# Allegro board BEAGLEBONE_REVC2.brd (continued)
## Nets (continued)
GPIO1_16: P9.15(8) U5.R13(GPMC_A0/GMII2_TXEN/RGMII2_TCTL/)
GPIO1_17: P9.23(12) U5.V14(GPMC_A1/GMII2_RXDV/RGMII2_RCTL/)
GPIO1_28: P9.12(31) U5.U18(GPMC_BE1N/GMII2_COL/GPMC_CSN6/M)
GPIO1_29: P8.26(38) U5.V6(GPMC_CSN0/GPIO1_29)
GPIO1_30: P8.21(11) U5.U9(GPMC_CSN1/GPMC_CLK/MMC1_CLK/PRT)
GPIO1_31: P8.20(35) U5.V9(GPMC_CSN2/GPMC_BE1N/MMC1_CMD/PR)
GPIO2_1: P8.18(34) U5.V12(GPMC_CLK/LCD_MEM_CLK/GPMC_WAIT1)
GPIO2_6: P8.45(23) R80.2 R100.1 U5.R1(LCD_DATA0/GPMC_A0//EHRPWM2A//PR)
GPIO2_7: P8.46(48) R81.2 R101.1 U5.R2(LCD_DATA1/GPMC_A1//EHRPWM2B//PR)
GPIO2_8: P8.43(22) R82.2 R102.1 U5.R3(LCD_DATA2/GPMC_A2//EHRPWM2_TRIP)
GPIO2_9: P8.44(47) R83.2 R103.1 U5.R4(LCD_DATA3/GPMC_A3//EHRPWM2_SYNC)
GPIO2_10: P8.41(21) R84.2 R104.1 U5.T1(LCD_DATA4/GPMC_A4//EQEP2A_IN//P)
GPIO2_11: P8.42(46) R85.2 R105.1 U5.T2(LCD_DATA5/GPMC_A5//EQEP2B_IN//P)
GPIO2_12: P8.39(20) R86.2 R106.1 U5.T3(LCD_DATA6/GPMC_A6/PR1_EDIO_DATA)
GPIO2_13: P8.40(45) R87.2 R107.1 U5.T4(LCD_DATA7/GPMC_A7/PR1_EDIO_DATA)
GPIO2_22: P8.27(14) U5.U5(LCD_VSYNC/GPMC_A8//PR1_EDIO_DAT)
GPIO2_23: P8.29(15) U5.R5(LCD_HSYNC/GPMC_A9//PR1_EDIO_DAT)
GPIO2_24: P8.28(39) U5.V5(LCD_PCLK/GPMC_A10//PR1_EDIO_DAT)
GPIO2_25: P8.30(40) U5.R6(LCD_AC_BIAS_EN/GPMC_A11//PR1_ED)
GPIO3_18: R202.2 U5.B12(MCASP0_ACLKR/EQEP0A_IN/MCASP0_A)
GPIO3_19: P9.27(14) U5.C13(MCASP0_FSR/EQEP0B_IN/MCASP0_AXR)
GPIO3_20: R221.2 U5.D13(MCASP0_AXR1/EQEP0_INDEX//MCASP1)
GPIO3_21: P9.25(13) U5.A14(MCASP0_AHCLKX/EQEP0_STROBE/MCAS)
GRN_C: P10.10(GRNC) R128.2
GRNA: P10.9(GRNA) U15.3(LED1/REGOFF)
HS_IND: TP8.1(TP) U11.16(HS_IND)
HUB_BIAS: R157.1 U11.26(RBIAS)
I2C0_SCL: R7.2 U2.28(SCL) U5.C16(I2C0_SCL/TIMER7/UART2_RTSN/ECAP) U7.6(SCL)
I2C0_SDA: R4.2 U2.27(SDA) U5.C17(I2C0_SDA/TIMER4/UART2_CTSN/ECAP) U7.5(SDA)
I2C1_SCL: P9.17(9) U5.A16(SPI0_CS0/MMC2_SDWP/I2C1_SCL/EHR)
I2C1_SDA: P9.18(34) U5.B16(SPI0_D1/MMC1_SDWP/I2C1_SDA/EHRP)
I2C2_SCL: P9.19(10) U5.D17(UART1_RTSN/TIMER5/DCAN0_RX/I2C2)
I2C2_SDA: P9.20(35) U5.D18(UART1_CTSN/TIMER6/DCAN0_TX/I2C2)
JTAG_EMU0: P7.13(EMU0) R170.2 R176.2 U5.C14(EMU0/GPIO3_7)
JTAG_EMU1: P7.14(EMU1) R171.2 R179.2 U5.B14(EMU1/GPIO3_8)
JTAG_TCK: R164.2 R178.1 R180.1 U5.A12(TCK)
JTAG_TDI: P7.3(TDI) R165.2 U5.B11(TDI)
JTAG_TDO: P7.7(TDO) R166.2 U5.A11(TDO)
JTAG_TMS: P7.1(TMS) R168.2 U5.C11(TMS)
JTAG_TRSTN: P7.2(TRSTN) R169.2 R186.1 U5.B10(NTRST)
LDO3: R19.1 U2.40(LDO3)
LDO4: R121.1 U2.43(LDO4)
LDO_PGOOD: R141.2 U2.46(LDO_PGOOD)
LED2: P10.12(YELA) R219.1 U15.2(LED2/NINTSEL)
LEDAA: D2.2(A) R96.2 TP10.1(TP)
LEDAC: D2.1(C) Q1.6(3)
LEDBA: D3.2(A) R97.2 TP11.1(TP)
LEDBC: D3.1(C) Q1.3
LEDCA: D4.2(A) R98.2 TP12.1(TP)
LEDCC: D4.1(C) Q2.6(3)
LEDDA: D5.2(A) R99.2 TP13.1(TP)
LEDDC: D5.1(C) Q2.3
MDIO_CLK: U5.M18(MDIO_CLK/TIMER5/UART5_TXD/UART3) U15.17(MDC)
MDIO_DATA: R131.2 U5.M17(MDIO_DATA/TIMER6/UART5_RXD/UART) U15.16(MDIO)
MMC0_CLKO: P4.5(CLOCK) R192.2 U5.G17(MMC0_CLK/GPMC_A24/UART3_CTSN/UA)
MMC0_CMD: P4.3(CMD) R191.2 U5.G18(MMC0_CMD/GPMC_A25/UART3_RTSN/UA)
MMC0_DAT0: P4.7(DAT0) R193.2 U5.G16(MMC0_DAT0/GPMC_A23/UART5_RTSN/U)
MMC0_DAT1: P4.8(DAT1) R194.2 U5.G15(MMC0_DAT1/GPMC_A22/UART5_CTSN/U)
MMC0_DAT2: P4.1(DAT2) R190.2 U5.F18(MMC0_DAT2/GPMC_A21/UART4_RTSN/T)
MMC0_DAT3: P4.2(CD/DAT3) R195.2 U5.F17(MMC0_DAT3/GPMC_A20/UART4_CTSN/T)
NINT/RXCLK/PHYAD1: R215.1 R216.1
NON_REM1: R154.2 R158.1 U11.13(NON_REM1)
NON_REM2: R155.2 R159.1 TP7.1(TP) U11.19(SUSP_IND/NON_REM0)
OSC0_IN: C26.1 R21.1 U5.V10(OSC0_IN) Y2.3 Y3.3
OSC0_OUT: R24.2 U5.U11(OSC0_OUT)
OSC0_OUT1: C27.1 R21.2 R24.1 Y2.1 Y3.1
OSC1_IN: C23.2 U5.A6(OSC1_IN) Y1.1
OSC1_OUT: R22.2 U5.A4(OSC1_OUT)
OSC1_OUT1: C24.2 R22.1 Y1.2
P_BYPASS: C5.2 U2.47(BYPASS)
P_INT_LDO: C4.2 U2.48(INT_LDO)
P_L1: L1.1 U2.20(L1)
P_L2: L2.1 U2.23(L2)
P_L3: L3.1 U2.31(L3)
P_MUXIN: R1.2 R2.1 U2.14(MUX_IN)
P_MUXOUT: R8.2 U2.16(MUX_OUT)
P_WAKEUP: R11.1 U2.13(WAKEUP)
PDDR_A0: R29.2 U5.F3(DDR_A0)
PDDR_A1: R25.2 U5.H1(DDR_A1)
PDDR_A2: R30.2 U5.E4(DDR_A2)
PDDR_A3: R26.2 U5.C3(DDR_A3)
PDDR_A4: R31.2 U5.C2(DDR_A4)
PDDR_A5: R32.2 U5.B1(DDR_A5)
PDDR_A6: R33.2 U5.D5(DDR_A6)
PDDR_A7: R34.2 U5.E2(DDR_A7)
PDDR_A8: R35.2 U5.D4(DDR_A8)
PDDR_A9: R36.2 U5.C1(DDR_A9)
PDDR_A10: R37.2 U5.F4(DDR_A10)
PDDR_A11: R38.2 U5.F2(DDR_A11)
PDDR_A12: R39.2 U5.E3(DDR_A12)
PDDR_A13: R40.2 U5.H3(DDR_A13)
PDDR_BA0: R41.2 U5.C4(DDR_BA0)
PDDR_BA1: R42.2 U5.E1(DDR_BA1)
PDDR_BA2: R43.2 U5.B3(DDR_BA2)
PDDR_CASN: R64.2 U5.F1(DDR_CASN)
PDDR_CKE: R62.2 U5.G3(DDR_CKE)
PDDR_CLK: R60.2 U5.D2(DDR_CK)
PDDR_CLKN: R61.2 U5.D1(DDR_NCK)
PDDR_CSN: R63.2 U5.H2(DDR_CSN0)
PDDR_D0: R44.2 U5.M3(DDR_D0)
PDDR_D1: R45.2 U5.M4(DDR_D1)
PDDR_D2: R46.2 U5.N1(DDR_D2)
PDDR_D3: R47.2 U5.N2(DDR_D3)
PDDR_D4: R48.2 U5.N3(DDR_D4)
PDDR_D5: R49.2 U5.N4(DDR_D5)
PDDR_D6: R50.2 U5.P3(DDR_D6)
PDDR_D7: R51.2 U5.P4(DDR_D7)
PDDR_D8: R52.2 U5.J1(DDR_D8)
PDDR_D9: R53.2 U5.K1(DDR_D9)
PDDR_D10: R54.2 U5.K2(DDR_D10)
PDDR_D11: R55.2 U5.K3(DDR_D11)
PDDR_D12: R56.2 U5.K4(DDR_D12)
PDDR_D13: R57.2 U5.L3(DDR_D13)
PDDR_D14: R58.2 U5.L4(DDR_D14)
PDDR_D15: R59.2 U5.M1(DDR_D15)
PDDR_DQM0: R67.2 U5.M2(DDR_DQM0)
PDDR_DQM1: R70.2 U5.J2(DDR_DQM1)
PDDR_DQS0: R68.2 U5.P1(DDR_DQS0)
PDDR_DQS1: R71.2 U5.L1(DDR_DQS1)
PDDR_DQSN0: R69.2 U5.P2(DDR_DQSN0)
PDDR_DQSN1: R72.2 U5.L2(DDR_DQSN1)
PDDR_ODT: R73.2 U5.G1(DDR_ODT)
PDDR_RASN: R65.2 U5.G4(DDR_RASN)
PDDR_WEN: R66.2 U5.B2(DDR_WEN)
PHY_VDDCR: C124.1 C125.1 U15.6(VDDCR)
PHY_XTAL1: C132.1 R140.2 R199.1 Y4.1
PHY_XTAL2: R140.1 R144.1 U15.4(XTAL2)
PHYX: C131.1 R144.2 Y4.2
PLLFILT: C145.1 U11.25(PLLFILT)
PMIC_INT: R10.2 R28.2 U5.B18(NNMI)
PMIC_INT_PU: R28.1 U14.7(2Y)
PMIC_INT_SRC: R10.1 R203.2 U2.45(INT) U14.1(2A) U14.2(2B)
PMIC_PGOOD: C25.1 R20.1 U2.26(PGOOD) U5.B15(PORZ)
PMIC_POWR_EN: U2.9(PWR_EN) U5.C6(PMIC_POWER_EN)
PWR_BUT: P9.9(5) U2.25(PB_IN)
PWR_LED: R6.1 U2.1(VLDO2)
PWR_LEDR: D1.2(A) R6.2 TP14.1(TP)
RBIAS: R145.1 U15.32(RBIAS)
RCLKIN: R199.2 R200.2 U15.5(XTAL1/CLKIN)
REFCLKO: R136.2 R209.2 U15.7(RXCLK/PHYAD1)
REMU_RSTN: R172.2 R182.1 U16.1(1A)
RESETN: C136.1 R156.2 U11.17(R\E\S\E\T\)
RMII1_COL: R207.1 U5.H16(GMII1_COL/RMII2_REFCLK/SPI1_SCL)
RMII1_CRS_DV: R139.1 U5.H17(GMII1_CRS/RMII1_CRS_DV/SPI1_D0/)
RMII1_REFCLK: R200.1 R201.2 R209.1
RMII1_RXCLK: R136.1 U5.L18(GMII1_RXCLK/UART2_TXD/RGMII1_RC)
RMII1_RXD0: R135.1 U5.M16(GMII1_RXD0/RMII1_RXD0/RGMII1_RD)
RMII1_RXD1: R132.1 U5.L15(GMII1_RXD1/RMII1_RXD1/RGMII1_RD)
RMII1_RXD2: R153.1 U5.L16(GMII1_RXD2/UART3_TXD/RGMII1_RD2)
RMII1_RXD3: R205.1 U5.L17(GMII1_RXD3/UART3_RXD/RGMII1_RD3)
RMII1_RXDV: R208.1 U5.J17(GMII1_RXDV/LCD_MEMORY_CLK/RGMII)
RMII1_RXERR: R137.1 U5.J15(GMII1_RXERR/RMII1_RXERR/SPI1_D1)
RMII1_TXCLK: R206.1 U5.K18(GMII1_TXCLK/UART2_RXD/RGMII1_TC)
RMII1_TXD0: U5.K17(GMII1_TXD0/RMII1_TXD0/RGMII1_TD) U15.22(TXD0)
RMII1_TXD1: U5.K16(GMII1_TXD1/RMII1_TXD1/RGMII1_TD) U15.23(TXD1)
RMII1_TXD2: U5.K15(GMII1_TXD2/DCAN0_RX/RGMII1_TD2/) U15.24(TXD2)
RMII1_TXD3: U5.J18(GMII1_TXD3/DCAN0_TX/RGMII1_TD3/) U15.25(TXD3)
RMII1_TXEN: U5.J16(GMII1_TXEN/RMII1_TXEN/RGMII1_TC) U15.21(TXEN)
RSVD3: R161.2 U11.15(VSS)
RTC_PORZ: R18.1 R141.1 R143.2 U5.B5(RTC_PORZ)
RTCK: P7.9(TCKRTN) R178.2
RXD0/MODE0: R124.1 R135.2 R198.1 U15.11(RXD0/MODE0)
RXD1/MODE1: R5.1 R123.1 R132.2 U15.10(RXD1/MODE1)
RXD2/RMIISEL: R153.2 R211.1 R212.1 U15.9(RXD2/RMIISEL)
RXD3/PHYAD2: R205.2 R213.1 R214.1 U15.8(RXD3/PHYAD2)
RXDV: R208.2 U15.26(RXDV)
RXER/PHYAD0: R125.1 R126.2 R137.2 U15.13(RXER/RXD4/PHYAD0)
RXN: C127.1 P10.2(RD-) R130.1 U15.30(RXN)
RXP: C126.1 P10.1(RD+) R129.1 U15.31(RXP)
SD_CD: P4.11(GND1) R196.1 R197.1
SPI1_CS0: P9.28(39) U5.C12(MCASP0_AHCLKR/EHRPWM0_SYNCI_O/M)
SPI1_D0: P9.29(15) U5.B13(MCASP0_FSX/EHRPWM0B//SPI1_D0/MM)
SPI1_D1: P9.30(40) U5.D12(MCASP0_AXR0/EHRPWM0_TRIPZONE_IN)
SPI1_SCLK: P9.31(16) U5.A13(MCASP0_ACLKX/EHRPWM0A//SPI1_SCL)
SYS_5V: C133.1 FB4.2 P9.7(4) P9.8(29) R3.2 R152.1 U2.7(SYS1) U2.8(SYS2) U9.2(IN#2) U9.3(IN#3)
SYS_RESETN: P9.10(30) R23.2 R27.1 U5.A10(NRESET_INOUT) U15.19(NRST)
SYS_VOLT: C6.1 C8.2 C9.2 C10.2 C17.2 C18.2 C19.2 R2.2 R3.1 U2.2(VINLDO) U2.21(VIN_DCDC1) U2.22(VIN_DCDC2) U2.32(VIN_DCDC3) U2.39(LDO3_IN) U2.42(LDO4_IN) U8.8(IN)
SYS_WARMRESETN: C101.1 R27.2 R163.2 S1.2(A2)
TCK: P7.11(TCK) R180.2
TCT_RCT: C130.1 P10.4(RCT) P10.5(TCT) R142.1
TDIS: P7.4(TDIS) R177.1
TESTOUT: TP6.1(TP) U5.A3(TESTOUT)
TIMER4: P8.7(4) U5.R7(GPMC_ADVN_ALE/TIMER4/GPIO2_2)
TIMER5: P8.9(5) U5.T6(GPMC_BE0N_CLE/TIMER5/GPIO2_5)
TIMER6: P8.10(30) U5.U6(GPMC_WEN/TIMER6/GPIO2_4)
TIMER7: P8.8(29) U5.T7(GPMC_OEN_REN/TIMER7/EMU4/GPIO2_)
TXCLK: R206.2 U15.20(TXCLK)
TXN: C129.1 P10.6(TD-) R134.1 U15.28(TXN)
TXP: C128.1 P10.3(TD+) R133.1 U15.29(TXP)
U5_H18: R201.1 U5.H18(RMII1_REFCLK/XDMA_EVENT_INTR2/S)
UART0_CTS: U5.E17(UART0_RTSN/UART4_TXD/DCAN1_RX/I) U12.40(BDBUS2)
UART0_RTS: U5.E18(UART0_CTSN/UART4_RXD/DCAN1_TX/I) U12.41(BDBUS3)
UART0_RX: U5.E16(UART0_TXD/SPI1_CS1/DCAN0_RX/I2C) U12.39(BDBUS1)
UART0_TX: U5.E15(UART0_RXD/SPI1_CS0/DCAN0_TX/I2C) U12.38(BDBUS0)
UART1_RXD: P9.26(38) U5.D16(UART1_RXD/MMC1_SDWP/DCAN1_TX/I2)
UART1_TXD: P9.24(37) U5.D15(UART1_TXD/MMC2_SDWP/DCAN1_RX/I2)
UART2_RXD: P9.22(36) U5.A17(SPI0_SCLK/UART2_RXD/I2C2_SDA/EH)
UART2_TXD: P9.21(11) U5.B17(SPI0_D0/UART2_TXD/I2C2_SCL/EHRP)
UART3_CTSN: P8.36(43) R90.2 R110.1 U5.U3(LCD_DATA10/GPMC_A14/EHRPWM1A/MC)
UART3_RTSN: P8.34(42) R91.2 R111.1 U5.U4(LCD_DATA11/GPMC_A15/EHRPWM1B/MC)
UART4_CTSN: P8.35(18) R92.2 R112.1 U5.V2(LCD_DATA12/GPMC_A16/EQEP1A_IN/M)
UART4_RTSN: P8.33(17) R93.2 R113.1 U5.V3(LCD_DATA13/GPMC_A17/EQEP1B_IN/M)
UART4_RXD: P9.11(6) U5.T17(GPMC_WAIT0/GM112_CRS/GPMC_CSN4/)
UART4_TXD: P9.13(7) U5.U17(GPMC_WPN/GMII2_RXERR/GPMC_CSN5/)
UART5_CTSN: P8.31(16) R94.2 R114.1 U5.V4(LCD_DATA14/GPMC_A18/EQEP1_INDEX)
UART5_RTSN: P8.32(41) R95.2 R115.1 U5.T5(LCD_DATA15/GPMC_A19/EQEP1_STROB)
UART5_RXD: P8.38(44) R89.2 R109.1 U5.U2(LCD_DATA9/GPMC_A13/EHRPWM1_SYNC)
UART5_TXD: P8.37(19) R88.2 R108.1 U5.U1(LCD_DATA8/GPMC_A12/EHRPWM1_TRIP)
USB0_DM: U5.N18(USB0_DM) U11.2(USBDM_DN2)
USB0_DP: U5.N17(USB0_DP) U11.3(USBDP_DN2)
USB0_ID: TP4.1(TP) U5.P16(USB0_ID)
USB0_VBUS: R152.2 U5.P15(USB0_VBUS) U16.4(2Y)
USB0_VBUS_PWR: U11.11(PRTPWR2) U16.3(2A)
USB1_DM: P2.2(P2) U5.R18(USB1_DM) U10.2(D-)
USB1_DP: P2.3(P3) U5.R17(USB1_DP) U10.1(D+)
USB1_DRVVBUS: R147.1 U5.F15(USB1_DRVVBUS/GPIO3_13) U9.4(EN)
USB1_ID: R146.1 U5.P17(USB1_ID)
USB1_OC: R148.2 U5.T16(GPMC_A10/GMII2_RXD1/RGMII2_RD1/) U9.5(O\C\)
USB1_VBUS: C134.1 P2.1(P1) U5.T18(USB1_VBUS) U9.6(OUT#6) U9.7(OUT#7) U9.8(OUT#8) U10.6(VBUS)
USB_DC: C2.1 P3.1(VB) R149.1 U2.12(USB)
USBDM_DN: P3.2(D-) U11.21(USBDM_UP)
USBDP_UP: P3.3(D+) U11.22(USBDP_UP)
USR0: Q1.2(5) R116.1 U5.V15(GPMC_A5/GMII2_TXD0/RGMII2_TD0/R)
USR1: Q1.5 R117.1 U5.U15(GPMC_A6/GMII2_TXCLK/RGMII2_TCLK)
USR2: Q2.2(5) R118.1 U5.T15(GPMC_A7/GMII2_RXCLK/RGMII2_RCLK)
USR3: Q2.5 R119.1 U5.V16(GPMC_A8/GMII2_RXD3/RGMII2_RD3/M)
VDCDC1: L1.2 R12.1 U2.19(VDCDC1)
VDCDC2: L2.2 R204.1 U2.24(VDCDC2)
VDCDC3: L3.2 R13.1 U2.29(VDCDC3)
VPP: U5.M5(VPP)
VREFP_ADC: C28.1 C29.1 C30.1 R78.2 U5.B9(VREFP)
VRTC: C20.1 C21.1 C98.1 R77.1 U2.3(VLDO1) U5.D7(VDDS_RTC) U17.1(2A) U17.2(2B) U17.8(VCC)
VRTC_DET: R17.1 U17.7(2Y)
VRTC_DET_OUT: R143.1 U17.3(2Y)
VRTC_DETB: C22.1 R17.2 U17.5(2A) U17.6(2B)
WAKEUP: R11.2 R77.2 U5.C5(EXT_WAKEUP)
WP: R210.2 TP2.1(TP) U7.7(WP)
XDMA_EVENT_INTR0: R183.1 U5.A15(EVENT_INTR0/TIMER4/CLKOUT1/SPI1)
XTALIN: C137.2 R160.1 U11.24(XTALIN/CLKIN) Y5.3
XTALOUT: C144.2 R160.2 U11.23(XTALOUT) Y5.1
XTIN: C153.2 U12.2(OSCIN) Y6.3(X3)
XTOUT: C155.2 U12.3(OSC0) Y6.1(X1)
YEL_C: P10.11(YELC) R16.2
N21360640: R220.1 U15.18(NINT/TXER/TXD4)

Pads without a net: NOREF 1; NOREF#11 1; NOREF#16 1; NOREF#25 1; NOREF#26 1; NOREF#27 1; P3 4; P5 3; P7 6; P10 7; U1 3; U2 15 17 44; U5 D3 F16 H4 M15 P18 R14 T13 U16 V17; U6 A2 E2 R3 R7; U8 2 6 7; U10 3 5; U11 5 8 12; U12 22 24 27 29 33 34 36 43 44 45 46 48 52 53 54 55 57 58 60; Y2 2 4; Y3 2 4; Y5 2 4; Y6 2 4

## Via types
v1: diameter 0.457, hole 0.203, TOP to BOTTOM, 799 vias
v2: diameter 0.559, hole 0.305, TOP to BOTTOM, 23 vias
v3: diameter 0.635, hole 0.305, TOP to BOTTOM, 5 vias

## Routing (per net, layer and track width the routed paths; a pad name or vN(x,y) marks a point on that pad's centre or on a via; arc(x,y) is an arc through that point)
3V3EXP_FB: length 6.3
  TOP w0.121: U8.3 12.95,8.88 12.7,8.64 v1(12.7,8.26)
  BOTTOM w0.121: C166.1 12.95,9.02 12.7,8.76 v1(12.7,8.26) 13.72,8.26 R150.1 R189.1
AGND: length 2.6
  TOP w0.203: U2.41 26,20.06 26.08,20.13 v1(26.08,20.95)
  BOTTOM w0.381: v1(26.08,20.95) 26.35,21.23 R15.1
DGND: length 423.3
  TOP w0.203: v2(26.8,16.51) 27,16.31 U2.30
  TOP w0.305: U12.25 v1(49.15,13.58) ; U17.4 31.88,21.79 32,21.67 v1(32,21.21) ; U12.47 41.84,17.73 v1(41.91,17.65) ; U5.A1 v1(56.33,26.8) ; v1(74.73,34.69) 74.33,34.29 U6.H8 ; v1(46.35,6.35) 46.35,6.79 46.33,6.81 U12.11 ; v1(46.35,6.35) v1(46.99,6.35) 47.12,6.35 47.33,6.57 U12.13 ; v1(46.35,6.35) 45.97,6.35 45.84,6.49 U12.10 ; v1(44.13,9.53) 43.33,8.73 U12.5 ; U5.H10 v1(48.73,33.49) U5.J10 ; v1(33.53,44.96) 33.77,45.2 Q1.4 ; v1(51.13,32.69) U5.H8 ; U5.L11 v1(47.93,35.89) U5.M12 ; v1(16.76,13.46) 16.5,13.2 U1.6 ; U5.A18 v1(42.33,27.09) ; v1(50.33,33.49) U5.J9 ; U6.A7 73.53,39.89 v1(73.93,39.49) U6.B8 ; Q1.1 32.27,47.51 v1(32.51,47.75) ; U5.M9 v1(50.33,36.69) U5.M8 ; U5.J11 v1(47.93,33.49) ; v1(73.93,33.09) 73.93,33.09 U6.J7 ; v1(47.13,31.89) U5.G12 47.69,32.13 48.17,32.13 U5.G11 ; U5.G9 v1(50.33,31.89) U5.F8 ; U5.M7 v1(51.93,35.89) U5.M6 ; U14.4 31.55,24.94 31.37,24.77 v1(31.11,24.77) ; v1(29.72,44.96) 29.96,45.2 Q2.4 ; U6.D8 v1(73.93,37.09) U6.E7 ; v1(47.62,17.65) 47.84,17.86 U12.35 ; U6.F2 v1(69.13,36.29) ; U5.J6 v1(52.73,33.49) U5.H6 ; v1(48.73,35.09) U5.K10 ; v1(48.73,35.09) U5.K11 ; v1(48.73,35.09) U5.L10 ; v1(50.33,35.09) U5.K9 ; U6.E3 v1(69.93,37.09) ; U12.51 38.56,16.09 38.35,15.88 v1(38.1,15.88) ; U6.B2 v1(69.13,39.49) ; U5.V1 v1(56.33,41.78) ; U6.N1 v1(68.33,29.89) ; U5.K7 U5.J7 v1(51.93,33.49) ; Q2.1 28.46,47.51 v1(28.7,47.75) ; U5.M14 v1(45.53,36.69) U5.N14 ; v1(47.13,32.69) U5.H12 ; v1(51.93,37.49) U5.N7 ; U5.L12 v1(47.13,35.89) U5.L13 ; U12.1 41.33,9.47 v1(41.27,9.53) ; U5.N10 v1(48.73,37.49) U5.N11 ; v2(22.23,40.01) 21.95,39.73 U11.6 ; v1(74.73,36.29) 74.33,35.89 U6.F8 ; v1(48.73,36.69) U5.M10 ; U5.V18 v1(41.91,41.09) ; v1(48.77,9.53) 48.33,9.09 U12.15 ; v1(51.13,33.49) U5.J8 ; U6.J3 v1(69.93,33.09) ; U5.G8 v1(50.33,32.69) U5.H9 ; U6.A3 v1(69.93,40.29) ; U1.2 v1(13.59,12.7) ; U6.D2 v1(69.13,37.89) ; U5.H7 v1(51.93,32.69) ; v1(49.15,14.61) 48.64,15.11 48.64,16.64 48.9,16.89 49.2,16.89 49.39,17.09 U12.32 ; U6.P9 v1(75.53,29.09) ; U6.H2 v1(69.13,34.69)
  TOP w0.381: C111.2 v1(79.25,37.09) ; C160.2 v1(80.52,35.56) ; C114.2 79.13,31.89 v1(79.25,32) ; R158.2 v1(27.56,42.55) ; C116.2 v1(64.33,42.55) ; C89.1 v1(79.69,42.55) ; C100.2 v1(11.94,48.26) ; C162.1 v1(38.1,19.56) ; C145.2 14.8,40.32 14.61,40.13 v1(14.61,39.69) ; v1(2.41,14.48) 2.41,15.49 D1.1 ; C110.2 78.91,38.69 v1(79.25,38.35) ; 36.83,41.27 36.83,42.29 37.08,42.55 C51.2 C52.1 ; 36.83,41.27 v1(36.83,40.64) v1(37.47,40.64) 37.47,41.15 C52.1 ; 36.83,41.27 C52.1 ; C117.2 v1(79.25,29.49) ; 64.77,45.85 v1(64.77,45.09) ; R79.1 v1(54.93,21.91) ; C163.1 38.61,6.99 v1(36.51,6.99) ; C101.2 6.99,42.16 6.73,42.42 v1(5.71,42.42) ; 48.58,45.85 v1(48.58,45.09) ; C113.2 v1(79.25,33.09) ; C159.2 v1(80.52,33.15) ; C146.2 v1(27.56,40.01) ; v3(14.73,8.32) 14.65,8.23 U8.4 ; U16.2 v1(30.86,41.91) ; C136.2 R159.2 v1(19.68,47.75) ; R161.1 v1(23.5,47.75) ; C137.1 v1(17.14,41.27) ; S1.1 2.16,41.13 v1(2.16,42.42) ; C112.2 v1(79.25,35.49) ; C144.1 v1(13.34,43.18) ; C109.2 v1(79.12,40.29) ; C115.2 v1(79.25,30.69)
  TOP w0.762: P2.4 70.54,20.34 C133.2
  LYR2_GND w0.889: TP1.1 61.69,21.05 ; TP1.1 61.69,19.59 ; TP1.1 60.23,21.05 ; TP1.1 60.23,19.59 ; 74.83,5.18 P9.46 ; P9.46 76.3,3.71 ; P9.46 74.83,3.71 ; P9.46 76.3,5.18 ; 73.76,2.64 P9.43 72.29,2.64 ; 72.29,3.71 P9.44 ; P9.44 72.29,5.18 ; P9.44 73.76,3.71 ; P9.44 73.76,5.18 ; P9.2 20.42,3.71 ; P9.2 18.95,5.18 ; P9.2 20.42,5.18 ; P9.2 18.95,3.71 ; P8.1 20.65,49.2 ; P8.1 18.72,49.2 ; P8.1 20.65,51.13 ; P8.1 18.72,51.13 ; P10.8 17.84,24.7 ; P10.8 17.84,26.1 ; P10.8 16.45,26.1 ; P10.8 16.45,24.7 ; 74.83,2.64 P9.45 76.3,2.64 ; 5.18,7.42 P5.2 ; P5.2 4.09,9.53 ; P5.2 6.27,9.53 ; P5.2 5.18,11.63 ; 20.42,51.97 P8.2 18.95,51.97 ; P2.4 74.15,21.11 ; P2.4 72.59,19.56 ; P2.4 72.59,21.11 ; P2.4 74.15,19.56 ; 20.65,2.87 P9.1 18.72,2.87
  BOTTOM w0.191: 29.75,32.86 31.78,32.86 31.94,33.02 R125.2
  BOTTOM w0.254: C82.2 49.5,28.58 48.73,29.35 v1(48.73,29.49) ; C62.1 46.44,31.2 v1(47.13,31.89) v1(47.13,32.69)
  BOTTOM w0.305: C39.2 51.64,33.78 v1(51.93,33.49) ; v1(48.73,33.49) 49.39,33.49 C40.2 ; v1(80.64,19.05) 80.51,18.91 U10.4 ; C93.2 52.73,30.98 v1(52.73,30.29) ; C91.2 52.73,34.18 v1(52.73,33.49) ; C45.2 47.82,31.89 v1(47.13,31.89) ; C58.1 v1(47.13,32.69) ; v1(51.93,35.89) C90.2 ; C92.2 v1(51.93,32.69) ; C64.1 50.04,31.6 v1(50.33,31.89) ; v1(50.33,35.09) 49.64,35.09 C38.2 ; v1(50.33,36.69) 50.04,36.98 C34.2 ; C96.2 v1(56.77,34.29) ; v1(44.13,9.53) R167.1 ; C37.2 48.44,34.8 v1(48.73,35.09) ; C41.2 v1(51.13,32.69) ; C35.2 51.24,37.49 v1(51.93,37.49) C65.1 ; C60.2 45.53,36 v1(45.53,36.69) 45.53,37.38 C33.2 ; C88.2 v1(47.93,35.89)
  BOTTOM w0.381: v1(24.77,5.84) 24.77,6.73 ; 24.77,6.73 25.91,6.73 26.16,6.99 26.16,8 ; 24.77,6.73 24.57,6.73 ; v1(51.13,43.18) C75.2 50.53,42.4 49.53,41.4 C43.1 ; R9.1 v1(28.26,20.32) C10.1 ; C149.1 31.37,41.4 v1(30.86,40.89) ; v2(23.5,15.24) 22.76,15.24 22.54,15.02 C2.2 21.84,14.48 21.46,14.86 C165.1 ; v2(23.5,16.51) 24.13,16.51 24.45,16.83 C17.1 C18.1 26.35,16.76 26.6,16.51 v2(26.8,16.51) ; C142.2 20.83,42.67 v2(20.95,42.55) ; C129.2 v1(10.67,27.94) ; C1.2 16.51,13.21 v1(16.76,13.46) ; R189.2 16.76,8 16.45,8.32 v3(15.75,8.32) ; R186.2 v1(59.63,6.99) ; C138.2 v2(22.23,42.55) ; R109.2 R108.2 v1(56.2,47.62) ; C156.2 62.1,15.24 v1(62.36,15.24) ; R146.2 41.25,39.09 40.51,38.35 v1(40.51,37.49) C78.2 ; C148.2 v1(44.13,14.61) ; U9.1 v1(75.59,13.63) ; C32.1 v1(37.21,32.77) ; v1(63.82,47.62) R100.2 R101.2 ; v1(54.93,21.91) 54.67,21.91 53.02,23.56 C97.2 C86.2 C98.2 C83.2 C85.2 C84.2 C57.2 46.74,24.26 46.48,24.51 v1(46.48,25.91) ; v1(76.71,37.85) 76.45,37.85 76.2,38.1 76.2,38.84 75.95,39.09 P4.9 ; C130.2 v1(10.67,30.48) ; v1(9.91,45.34) 9.19,46.05 P3.5 ; 20.32,8 20.32,6.6 v1(19.68,5.97) ; v1(36.83,40.64) v1(37.47,40.64) ; v1(36.83,40.64) 36.83,40.13 37.08,39.88 C61.2 37.47,40.01 v1(37.47,40.64) ; v1(36.83,40.64) 36.83,41.53 C69.2 37.47,41.66 v1(37.47,40.64) ; v1(14.61,39.69) 14.61,39.3 14.85,39.05 R157.2 ; C106.2 v1(65.28,35.49) ; R127.2 35.43,35.56 v1(35.18,35.81) ; U7.2 26.16,8 ; 26.16,8 26.16,9.27 ; U13.2 32.58,9.84 32.17,9.44 32.17,7.87 ; C54.2 37.21,25.78 v1(37.21,26.16) ; 71.82,13.34 v1(71.82,12.06) ; 71.82,13.34 69.7,13.34 ; 71.82,13.34 71.82,15.88 ; v1(71.82,12.06) P7.10 ; v1(71.82,12.06) v1(71.82,10.79) P7.8 ; R103.2 R102.2 v1(61.91,47.62) ; R147.2 v1(76.83,19.68) ; v1(36.2,14.86) C15.1 ; v1(48.77,9.53) 49.53,10.29 50.16,10.29 ; v1(19.05,23.75) C4.1 C5.1 ; v1(23.37,35.81) 23.37,35.31 23.94,34.73 C122.2 ; R128.1 v1(6.22,30.23) ; v1(6.22,30.23) v1(6.22,29.46) ; v1(6.22,30.23) 5.4,30.23 R138.1 5.4,29.46 v1(6.22,29.46) ; C147.2 49.37,15.37 49.15,15.14 v1(49.15,14.61) ; C155.1 v1(37.47,9.53) C153.1 ; C3.1 v1(10.16,13.97) C7.2 ; C76.2 C77.2 C79.2 41.42,27.67 41.91,27.18 41.91,27.09 ; C76.2 40.91,29.89 40.56,29.54 v1(40.51,29.54) ; C76.2 C49.2 ; v1(23.37,20.95) 23.62,21.21 23.62,21.65 C135.1 ; C164.1 v1(46.99,6.35) v1(46.35,6.35) 45.72,6.35 45.4,6.67 C161.2 ; R75.2 v1(64.01,33.66) ; R1.1 22.99,10.54 U7.4 25.91,10.54 26.16,10.29 26.16,9.27 ; v1(58.1,47.62) R106.2 R107.2 ; C66.1 v1(54.33,43.15) ; R118.2 v1(29.72,44.96) ; v1(65.28,33.09) C107.2 C118.2 ; v1(33.97,20.45) C50.1 32.85,19.3 ; C158.2 v1(42.86,6.35) ; C73.2 40.71,32.89 v1(40.51,32.69) ; C73.2 C71.1 40.91,33.89 v1(40.51,34.29) ; C73.2 C48.2 C49.2 ; v2(26.04,31.5) 26.42,31.11 26.42,30.61 C124.2 ; v2(26.04,31.5) 25.78,31.75 C120.2 C119.2 ; v2(26.04,31.5) 26.29,31.75 C125.2 ; v1(21.46,19.56) 22.23,19.56 C19.1 ; v1(19.68,29.53) R145.2 R216.2 ; R212.2 R5.2 R198.2 ; R212.2 R214.2 36.89,29.53 C31.1 37.3,29.12 v1(37.3,27.94) ; R212.2 v1(36.45,30.48) ; C63.1 42.42,41.4 42.11,41.09 v1(41.91,41.09) 41.62,41.09 41.42,40.89 C80.2 ; v1(6.22,29.46) R16.1 R219.2 ; v1(52.39,47.62) R113.2 R111.2 ; v1(60.01,47.62) R104.2 R105.2 ; C53.2 37.21,24 v1(37.21,23.75) ; C46.2 42.99,20.51 v1(42.99,20.32) ; C131.2 v1(21.46,25.53) ; C9.1 C8.1 26.1,15.24 v2(25.15,15.24) ; 48.58,45.85 v1(48.58,45.09) ; v1(50.48,47.62) R114.2 R115.2 ; R15.2 v1(26.35,23.81) ; 32.17,7.87 v1(33.15,7.87) ; 32.17,7.87 C102.2 ; v1(33.02,20.45) 32.85,20.28 32.85,19.3 ; R119.2 v1(28.7,47.75) ; C104.2 v1(65.28,38.69) ; C126.2 v1(10.67,34.29) ; R20.2 v1(29.21,27.3) ; R20.2 C157.1 ; R20.2 C25.2 ; v1(40.51,35.89) C81.2 C36.2 ; C108.2 v1(65.28,28.29) ; C128.2 v1(10.67,31.75) ; R117.2 v1(32.51,47.75) ; C103.2 v1(65.28,40.29) ; P4.6 80.76,35.32 v1(80.52,35.56) ; C150.2 v1(41.91,17.65) ; C20.2 v1(19.68,20.32) ; C152.2 46.04,14.85 45.79,14.61 v1(45.34,14.61) ; C21.2 v1(34.92,21.21) ; C94.2 v1(79.69,42.55) ; C95.2 v1(64.33,42.55) ; C134.2 v1(81.92,19.68) ; P7.16 71.82,15.88 ; 71.82,15.88 71.82,18.1 71.5,18.41 P7.20 ; C121.2 25.78,33.02 v2(26.04,33.27) 26.29,33.02 C123.2 27.11,33.4 27.37,33.66 28.96,33.66 29.75,32.86 ; R177.2 C154.2 v1(59.63,9.53) ; v1(54.29,47.62) R112.2 R110.2 ; C22.2 v1(33.97,23.81) ; C70.1 v1(52.73,43.18) ; v2(19.68,40.01) 19.56,39.88 C143.2 ; C127.2 v1(10.67,33.02) ; C105.2 v1(65.28,37.09) ; v1(40.51,31.19) 40.51,31.09 40.71,30.89 C49.2 ; C55.2 v1(30.16,19.94) ; C132.2 26.35,24.96 26.67,24.64 27.06,24.64 27.3,24.39 v1(27.3,23.81) ; R18.2 v1(32.07,27.3) ; R116.2 v1(33.53,44.96) ; R220.2 v1(31.75,39.24) C72.2 ; TP1.1 R76.1 ; C141.2 22.1,39.88 v2(22.23,40.01) C139.2 ; 26.16,9.27 24.57,9.27 ; C56.2 v1(46.33,43.18) ; C56.2 C74.2 ; C56.2 46.46,42.27 47.8,42.27 47.93,42.4 C99.2 ; 32.85,19.3 C14.1 31.62,19.43 31.62,20.17 31.87,20.42 v1(32,20.42) ; v3(15.24,9.21) 15.43,9.02 C6.2 ; FB3.2 v1(47.62,17.65) ; C140.2 v2(22.23,41.27) ; C136.2 v1(20.95,47.75) ; 64.77,45.85 v1(64.77,45.09)
  BOTTOM w0.762: P8.1 P8.2 ; P9.1 P9.2 ; C44.1 41.91,27.09 v1(42.33,27.09) ; P9.45 P9.46
  vias: v1(48.64,21.84) v2(19.68,42.55) v2(19.68,41.27) v2(20.95,41.27) v2(20.95,40.01) v2(25.15,32.38) v2(25.15,16.51) v2(26.04,32.38) v2(26.92,32.38) v2(78.74,15.24) v2(78.74,13.97) v2(80.01,15.24) v2(80.01,13.97) v3(14.73,10.1) v3(15.75,10.1)
GND_EARTH: length 193.8
  TOP w0.381: S1.3 v1(3.81,38.1)
  TOP w0.889: MTG4.1 82.41,50.03 ; MTG4.1 82.41,46.49 ; MTG4.1 78.88,46.49 ; MTG4.1 78.88,50.03 ; 78.88,8.12 MTG2.1 ; MTG2.1 78.88,4.58 ; MTG2.1 82.41,8.12 ; MTG2.1 82.41,4.58 ; 12.84,4.94 MTG1.1 ; MTG1.1 16.37,4.94 ; MTG1.1 16.37,1.41 ; MTG1.1 12.84,1.41 ; 12.84,53.2 MTG3.1 ; MTG3.1 12.84,49.67 ; MTG3.1 16.37,53.2 ; MTG3.1 16.37,49.67
  LYR2_GND w0.889: MTG4.1 82.41,50.03 ; MTG4.1 78.88,46.49 ; MTG4.1 82.41,46.49 ; MTG4.1 78.88,50.03 ; MTG2.1 82.41,8.12 ; MTG2.1 78.88,8.12 ; MTG2.1 78.88,4.58 ; MTG2.1 82.41,4.58 ; MTG1.1 16.37,1.41 ; MTG1.1 12.84,4.94 ; MTG1.1 12.84,1.41 ; MTG1.1 16.37,4.94 ; MTG3.1 16.37,53.2 ; MTG3.1 16.37,49.67 ; MTG3.1 12.84,53.2 ; MTG3.1 12.84,49.67
  LYR5_PWR w0.889: MTG3.1 16.37,53.2 ; MTG3.1 12.84,49.67 ; MTG3.1 12.84,53.2 ; MTG3.1 16.37,49.67 ; 12.84,4.94 MTG1.1 ; MTG1.1 16.37,1.41 ; MTG1.1 16.37,4.94 ; MTG1.1 12.84,1.41 ; MTG2.1 82.41,8.12 ; MTG2.1 82.41,4.58 ; MTG2.1 78.88,8.12 ; MTG2.1 78.88,4.58 ; 78.88,46.49 MTG4.1 ; MTG4.1 78.88,50.03 ; MTG4.1 82.41,46.49 ; MTG4.1 82.41,50.03
  BOTTOM w0.381: v1(1.91,30.23) 2.86,30.23 R138.2 2.86,29.46 v1(1.91,29.46) ; 84.58,41.15 72.14,41.15 70.94,39.95 P4.10 ; P4.12 72.01,29.62 72.52,29.11 72.52,24.51 73.66,23.37 76.04,23.37 P2.6
  BOTTOM w0.889: 12.84,1.41 MTG1.1 ; MTG1.1 16.37,4.94 ; MTG1.1 12.84,4.94 ; MTG1.1 16.37,1.41 ; 78.88,4.58 MTG2.1 ; MTG2.1 82.41,4.58 ; MTG2.1 82.41,8.12 ; MTG2.1 78.88,8.12 ; 12.84,53.2 MTG3.1 ; MTG3.1 12.84,49.67 ; MTG3.1 16.37,49.67 ; MTG3.1 16.37,53.2 ; MTG4.1 82.41,50.03 ; MTG4.1 78.88,46.49 ; MTG4.1 78.88,50.03 ; MTG4.1 82.41,46.49 ; 85.41,26.97 P4.13 85.41,25.17 ; 85.41,38.07 P4.14 85.41,39.87
  vias: v1(3.05,50.8) v1(3.05,38.1) v1(3.81,50.8) v1(7.24,50.8) v1(7.24,38.1) v1(8,50.8) v1(8,38.1)
GND_OSC0: length 6.8
  TOP w0.305: U5.V11 48.33,41.59 v1(47.12,42.8)
  TOP w0.381: v1(43.69,48.13) 44.07,48.13 44.45,47.75 C26.2 ; v1(41.4,44.58) 40.64,45.34 40.64,45.85
  BOTTOM w0.381: 47.12,44.01 v1(47.12,42.8)
GND_OSC1: length 12
  TOP w0.305: 53.13,27.13 U5.A5
  TOP w0.381: 56.52,19.94 56.52,20.38 55.94,20.95 54.61,20.95 53.34,22.23 53.34,25.59 53.63,25.88 53.63,26.63 53.13,27.13
  BOTTOM w0.381: C24.1 v1(57.78,16.51) ; C23.1 v1(55.24,16.51)
GNDA_ADC: length 43.6
  TOP w0.305: U5.A9 49.93,27.05 ; v1(51.13,30.29) U5.E8
  TOP w0.381: v1(47.62,21.84) C30.2 C29.2 C28.2 C87.2 ; 49.93,27.05 49.93,26.8 50.29,26.44 50.29,25.27 51.09,24.48 51.09,22.83 50.93,22.67 C87.2 ; C87.2 v1(50.48,21.84)
  LYR4 w0.381: P9.34 58.29,6.48 58.29,8.76 54.61,12.45 54.61,14.35 52.2,16.76 52.2,19.68 50.48,21.4 v1(50.48,21.84) 50.48,27.5 49.66,28.32 49.66,29.84 50.1,30.29 v1(51.13,30.29)
  BOTTOM w0.381: FB3.1 v1(47.62,21.84)
VBUS_DET: length 3.4
  TOP w0.121: U11.18 v1(20.95,44.96)
  BOTTOM w0.121: v1(20.95,44.96) 20.95,45.85 19.68,45.85
VDD_1V8: length 68.8
  TOP w0.305: U5.N6 v1(51.93,36.69) ; U5.E14 v1(45.53,30.29) ; v1(45.53,38.29) U5.P14 ; U5.E9 v1(50.33,31.09) U5.F9 ; U5.E6 v1(51.93,30.29) U5.E7 ; v1(47.13,35.09) U5.K13 ; v1(50.33,38.29) U5.P9 ; v1(43.93,37.49) U5.N16 ; v1(48.73,30.29) U5.D10 ; v1(43.93,39.09) U5.R16
  TOP w0.508: v1(19.56,11.56) 19.43,11.68 R12.2 TP15.1 20.32,13.46 v1(20.57,13.21)
  LYR3 w0.762: v1(50.8,17.65) v1(50.04,17.65) 48.98,18.71 41.53,18.71 40.98,18.16 34.92,18.16 30.73,13.97 30.73,12.45 29.84,11.56 21.46,11.56 ; 21.46,11.56 v1(21.46,12.45) 20.57,12.45 ; 21.46,11.56 20.57,11.56 ; v1(20.57,13.21) 20.57,12.45 ; 20.57,12.45 20.57,11.56 ; 20.57,11.56 v1(19.56,11.56)
  BOTTOM w0.121: 45.13,38.69 45.13,40.34
  BOTTOM w0.305: C80.1 42.7,40.32 v1(43.93,39.09) ; v1(48.73,30.29) 49.42,29.6 C82.1 49.66,29.6 50.33,30.26 v1(50.33,31.09) ; v1(43.93,37.49) C78.1 ; v1(45.53,38.29) 45.13,38.69 ; 45.13,40.34 44.73,40.74 C74.1
  BOTTOM w0.381: v1(36.83,39.24) 36.83,38.42 FB1.1 37.47,38.41 v1(37.47,39.24) v1(36.83,39.24) ; v1(36.83,39.24) C72.1 ; v1(50.04,17.65) v1(50.8,17.65) 50.67,17.78 50.67,18.54 50.48,18.74 FB2.2 50.04,18.61 v1(50.04,17.65)
  vias: v1(43.93,31.09)
VDD_1V8FT: length 34.9
  TOP w0.305: C162.2 39.49,17.79 U12.49 40.51,17.09 41.4,16.2 v1(41.4,12.95) 41.4,10.41 40.57,9.58 U12.64 39.49,8.88 C163.2 ; U12.37 46.84,17.53 46.74,17.43 v1(46.74,16.38) ; v1(46.84,9.53) U12.12
  LYR3 w0.381: v1(46.84,9.53) 46.84,10.8 46.59,11.05 43.43,11.05 41.53,12.95 v1(41.4,12.95)
  BOTTOM w0.381: C164.2 46.99,9.37 v1(46.84,9.53) 46.74,9.62 v1(46.74,16.38) C152.1
VDD_3V3A: length 96.2
  TOP w0.203: U2.18 25.2,12.89 24.75,12.45 v1(24.64,12.45)
  TOP w0.305: v1(44.73,39.09) U5.R15 ; U5.P12 v1(47.13,38.29) ; U5.P5 v1(53.53,38.29) ; U5.K14 v1(46.33,35.09) U5.L14 ; U5.J14 v1(45.53,33.49) U5.H14 ; v1(44.73,37.49) U5.N15 ; U5.P10 v1(48.73,38.29) U5.P11 ; U5.G14 v1(45.53,31.89) U5.F14 ; U5.E10 v1(48.73,31.09) U5.E11 v1(47.93,30.29) U5.E12 v1(47.13,30.29) U5.E13 ; U5.P6 v1(52.73,38.29) ; U5.P13 v1(46.33,38.29) ; U5.P8 U5.P7 v1(51.93,38.29) ; U5.N5 v1(52.73,36.69)
  TOP w0.381: v1(59.05,47.62) R85.1 R84.1 ; R94.1 R91.1 ; R91.1 v1(51.44,47.62) ; R91.1 R93.1 ; v1(83.69,31.75) 83.69,32.77 C159.1 83.69,33.53 v1(83.69,34.54) ; v1(83.69,31.75) v1(83.69,30.73) ; v1(83.69,31.75) R191.1 ; C67.2 v1(48.58,47.62) ; R195.1 v1(83.69,30.73) ; v1(83.69,30.73) v1(83.69,29.72) R190.1 ; C68.2 v1(64.77,47.62) ; v1(83.69,34.54) v1(83.69,35.56) ; v1(83.69,34.54) R192.1 ; v1(57.15,47.62) R87.1 R86.1 ; v1(83.69,35.56) C160.1 ; v1(83.69,35.56) v1(83.69,36.58) ; 39.37,41.27 v1(39.37,40.64) v1(38.73,40.64) 38.73,41.15 C52.2 ; 39.37,41.27 C52.2 ; 39.37,41.27 39.37,42.29 39.12,42.55 C51.1 C52.2 ; v1(55.24,47.62) R89.1 R88.1 ; v1(53.34,47.62) R90.1 R92.1 ; v1(10.29,40.32) 10.16,40.45 R23.1 ; U8.5 16.71,7.29 v1(18.03,5.97) ; R193.1 v1(83.69,36.58) ; v1(83.69,36.58) v1(83.69,37.59) R194.1 ; R82.1 R83.1 v1(60.96,47.62) ; R80.1 R81.1 v1(62.87,47.62) ; R95.1 v1(49.53,47.62)
  LYR4 w0.381: v1(18.03,5.97) 17.4,6.6 17.4,14.99 v1(19.18,16.76)
  BOTTOM w0.305: v1(44.73,37.49) 43.73,36.49 43.62,36.49 43.02,35.89 C81.1 ; v1(46.33,35.09) 46.44,35.2 C60.1 ; v1(45.53,33.49) 45.53,32.8 C58.2 45.53,32.58 v1(45.53,31.89) 45.53,31.2 C62.2 ; C65.2 53.53,37.6 v1(53.53,38.29) ; v1(48.73,38.29) 49.42,38.98 C43.2 ; v1(48.73,31.09) 49.24,30.58 C64.2
  BOTTOM w0.381: v1(38.73,40.64) 38.73,40.01 C61.1 39.12,39.88 39.37,40.13 v1(39.37,40.64) ; v1(38.73,40.64) 38.73,41.66 38.99,41.91 39.37,41.53 v1(39.37,40.64) ; v1(38.73,40.64) v1(39.37,40.64) ; v1(83.69,31.75) 83.69,33.12 ; 83.69,33.12 P4.4 ; 83.69,33.12 v1(83.69,34.54) ; R4.1 R7.1 v1(32.38,13.46) ; C63.2 v1(40.51,41.91) ; C67.2 v1(48.58,47.62) ; R19.2 20.57,16.89 C165.2 20.19,16.76 v1(19.18,16.76) ; v1(47.5,26.16) 47.31,25.97 C57.1 ; C68.2 v1(64.77,47.62)
VDD_3V3B: length 96.5
  TOP w0.191: R187.1 35.43,8.92 35.02,9.33 35.01,9.33 34.94,9.4 34.8,9.4 34.42,9.78 R173.1
  TOP w0.254: U15.12 28.95,32.14 v1(29.34,32.14) ; v1(33.97,27.3) 34.29,27.3 34.42,27.18 34.42,26.86 U14.8
  TOP w0.305: U11.10 24.24,40.77 v1(24.38,40.64) ; v1(40.89,13.58) U12.56 38.1,13.58 37.72,13.21 R181.1 ; v1(24.38,43.18) 23.98,42.78 U11.14 ; v1(19.68,44.69) 19.96,44.42 U11.20 ; U12.42 44.33,17.86 v1(44.13,17.65) ; U11.4 v1(20.95,37.85) ; v1(49.15,11.09) U12.20 ; U12.28 49.56,15.09 49.15,15.49 v1(49.15,16.38) 49.53,16.38 49.73,16.58 U12.31 ; v1(17.65,39.05) 17.65,40.01 17.92,40.28 U11.27
  TOP w0.381: R155.1 v1(18.41,47.75) ; v1(35.05,41.91) U16.5 ; R187.1 v1(36.51,8.89) ; R156.1 v1(22.23,47.75) ; v1(62.29,10.79) 61.28,11.81 R176.1 ; R154.1 v1(27.56,41.27) ; R173.1 R174.1
  LYR4 w0.381: v1(69.09,21.34) 69.09,21.34 69.34,21.59 82.55,21.59 83.19,20.95 v1(83.19,19.68)
  BOTTOM w0.191: R126.1 35.43,33.69 35.31,33.81 33.5,33.81 33.02,34.29 v1(32.64,34.29) ; 31.94,31.91 29.56,31.91 v1(29.34,32.14)
  BOTTOM w0.381: R121.2 v1(25.4,23.81) 24,23.81 C135.2 ; v1(29.34,32.14) 29.34,32.38 28.7,33.02 C123.1 ; R196.2 69.34,21.59 69.09,21.34 v1(69.09,21.34) ; C150.1 41.91,14.86 v1(42.16,14.61) ; v1(20.95,37.85) 21.08,37.97 C141.1 ; 29.78,6.73 31.37,6.73 C102.1 v1(32.38,6.86) ; v1(36.51,8.89) U13.6 ; v1(28.26,24.77) C157.2 ; R203.1 v1(30.16,23.81) ; R162.1 v1(33.97,27.3) 34.42,27.75 R213.2 ; R124.2 R123.2 R211.2 ; R210.1 v1(31.5,11.75) ; v1(19.68,25.53) 19.68,27.05 20.26,27.62 R215.2 ; C151.1 49.37,11.3 v1(49.15,11.09) 48.93,11.3 R175.1 ; C147.1 v1(49.15,16.38) ; C149.2 34.54,41.4 v1(35.05,41.91) ; P7.5 v1(62.29,9.53) C154.1 ; v1(45.4,13.84) FB6.1 FB7.1 v1(43.18,13.84) ; C139.1 24.38,40.06 v1(24.38,40.64) 24.38,41.22 C140.1 ; v1(19.68,44.69) 19.81,44.56 C142.1 ; C138.1 24.38,42.61 v1(24.38,43.18) ; R122.2 v1(32.64,34.29) ; v1(40.89,13.58) 40.26,13.58 40.01,13.84 FB8.1 ; C143.1 v1(17.65,39.05) ; R131.1 C122.1 ; R148.1 v1(83.19,19.68) ; R179.1 v1(62.29,10.79) ; C148.1 v1(44.13,17.65) ; FB5.1 v1(28.45,37.21)
VDD_3V3EXP: length 20.3
  TOP w0.381: v1(13.72,10.79) 13.72,10.23 U8.1
  LYR4 w0.381: 13.72,7.49 v1(13.72,10.79) ; 13.72,7.49 v1(12.7,7.49) ; 13.72,7.49 15.49,7.49 18.22,4.76 18.22,4 18.92,3.3 21.08,3.3 P9.4
  BOTTOM w0.381: R150.2 v1(12.7,7.49) ; v1(13.72,10.79) 13.72,10.79 13.46,10.53 13.46,10.03
  BOTTOM w0.762: P9.3 P9.4
VDD_5V: length 18
  LYR3 w0.762: P9.6 23.75,5.46 23.75,6.73 21.97,8.51 19.43,8.51 17.78,10.16 17.78,10.88 17.14,11.52 16.11,11.52 15.49,12.13 v1(15.49,13.97)
  BOTTOM w0.762: P9.5 P9.6
  vias: v1(14.73,13.97)
VDD_ADC: length 35.7
  TOP w0.305: v1(51.13,29.49) U5.D8
  TOP w0.381: C87.1 50.48,24.31 50.03,24.77 R78.1 49.64,24.84 v1(49.64,26.16)
  LYR3 w0.381: v1(49.64,26.16) 49.66,26.18 49.66,29.72 50.04,30.1 50.52,30.1 v1(51.13,29.49)
  LYR4 w0.381: P9.32 57.78,8.51 54.1,12.19 54.1,14.1 51.69,16.51 51.69,19.3 49.66,21.34 v1(49.66,21.84) 49.64,21.87 v1(49.64,26.16)
  BOTTOM w0.381: v1(49.66,21.84) 49.66,21.14 FB2.1
VDD_CORE: length 33.3
  TOP w0.305: U5.K6 v1(52.73,35.09) U5.L6 ; v1(47.93,35.09) U5.K12 ; v1(50.33,35.89) U5.L9 ; U5.K8 v1(51.13,35.09) U5.L7 ; U5.N9 v1(50.33,37.49) U5.N8 ; v1(51.13,35.89) U5.L8 ; v1(48.73,32.69) U5.G10 ; U5.F7 v1(51.93,31.09) ; U5.M13 v1(46.33,36.69) ; U5.J12 v1(47.13,33.49) ; v1(51.93,31.89) U5.G7 ; U5.N12 v1(47.13,36.69) U5.N13 ; U5.G6 v1(52.73,31.89) U5.F6 ; U5.H11 v1(47.93,32.69) ; U5.M11 v1(48.73,35.89)
  TOP w0.508: R13.2 TP17.1 36.7,18.54 36.7,20.32 ; 36.7,20.32 v1(36.2,20.32) ; 36.7,20.32 v1(37.21,20.32)
  BOTTOM w0.305: C39.1 50.73,34.4 U5.K8 v1(51.13,35.09) v1(52.73,35.09) ; v1(47.13,36.69) v1(46.33,36.69) 46.33,37.38 C33.1 ; C41.1 51.24,31.09 v1(51.93,31.09) v1(51.93,31.89) v1(52.73,31.89) ; v1(47.93,32.69) v1(47.13,33.49) 47.42,33.78 C37.1 47.42,34.58 v1(47.93,35.09) ; v1(48.73,32.69) 48.84,32.58 C40.1 ; v1(43.93,35.89) 43.64,35.89 42.74,34.99 42.54,34.99 C36.1 ; v1(50.33,35.89) 49.64,35.89 C38.1 49.42,35.89 v1(48.73,35.89) ; C35.1 v1(51.13,35.89) ; v1(50.33,37.49) 49.93,37.89 49.64,37.89 C34.1
  BOTTOM w0.381: C49.1 C48.1 v1(43.13,31.89)
  vias: v1(38.99,32.77) v1(38.99,32) v1(38.99,30.48)
VDD_FTREGIN: length 3.5
  TOP w0.305: U12.50 38.17,16.58 v1(38.1,16.51)
  BOTTOM w0.381: v1(38.1,16.51) 38.41,16.82 FB8.2
VDD_FTVPHY: length 4.7
  TOP w0.305: U12.4 42.84,9.18 v1(43.18,9.53)
  BOTTOM w0.381: C158.1 42.86,9.21 v1(43.18,9.53) FB7.2
VDD_FTVPLL: length 4.5
  TOP w0.305: U12.9 45.33,9.46 v1(45.4,9.53)
  BOTTOM w0.381: FB6.2 v1(45.4,9.53) C161.1
VDD_LED: length 8.4
  TOP w0.381: 9.08,47.47 R96.1 ; 9.08,47.47 C100.1 10.92,45.91 FB4.1 ; 9.08,47.47 R97.1 R98.1 R99.1
VDD_MPU: length 33.8
  TOP w0.305: U5.F10 v1(48.73,31.89) U5.F11 U5.F12 v1(47.13,31.09) U5.F13 v1(46.33,31.89) U5.G13 46.62,32.4 46.62,32.98 U5.H13 v1(46.33,33.49) U5.J13
  TOP w0.508: R204.2 32.77,12.7 33.15,13.08 v1(35.43,13.08) v1(36.2,13.08)
  BOTTOM w0.203: v1(48.73,31.89) 48.73,31.71 48,30.98 C45.1
  BOTTOM w0.305: v1(47.13,31.09) 47.24,30.98 C45.1
  BOTTOM w0.381: C46.1 40.51,21.08 ; v1(46.33,33.49) 46.44,33.6 C47.1
  BOTTOM w0.762: 33.97,13.08 v1(35.43,13.08) v1(36.2,13.08) 36.7,13.08 37.08,13.46 37.08,17.4 39.62,19.94 39.62,20.7 40.01,21.08 40.51,21.08 40.51,24.13 ; 40.51,24.13 v1(40.51,26.16) ; 40.51,24.13 C44.2
VDD_MPUON: length 2.9
  TOP w0.121: TP5.1 56.26,25.65 56.26,26.16 55.88,26.54 55.88,27.14 U5.A2
VDD_PHYA: length 16.9
  TOP w0.254: v1(23.94,28.96) 24.28,29.3 U15.1 ; U15.27 22.95,33.14 22.73,33.35 22.73,33.53 22.23,34.04 v1(22.23,34.29)
  BOTTOM w0.381: R142.2 v1(10.67,29.21) ; R133.2 v1(19.68,32.38) ; R134.2 v1(19.68,33.34) ; C120.1 C121.1 23.5,33.02 v1(22.23,34.29) 22.75,34.82 22.75,36.09 23.88,37.21 FB5.2 ; R130.2 v1(19.68,31.43) ; R129.2 v1(19.68,30.48) ; C119.1 v1(23.94,28.96)
VDD_PLL: length 15.1
  TOP w0.305: U5.H15 v1(44.73,32.69) ; U5.R10 49.13,38.7 v1(48.73,39.09) U5.R11 v1(47.93,38.29)
  LYR3 w0.381: v1(48.73,39.09) v1(47.93,38.29) 47.1,37.47 45.47,37.47 45.04,37.04 45.03,37.04 44.95,36.96 43.92,36.96 43.66,36.7 43.66,36.47 43.32,36.13 42.89,36.13 v1(42.33,36.69)
  BOTTOM w0.305: C88.1 v1(47.93,38.29)
  BOTTOM w0.635: FB1.2 39.37,37.78 39.37,37.34 40.02,36.69 v1(42.33,36.69)
VDD_RTC: length 5.3
  TOP w0.305: v1(52.73,29.49) U5.D6
  BOTTOM w0.121: C97.1 52.64,25.65 52.64,26.48 52.83,26.67 52.83,28.23 53.13,28.52 53.13,28.62 53.13,29.09 v1(52.73,29.49)
VDDS_DDR: length 121.9
  TOP w0.305: U6.J1 v1(68.33,33.09) ; U6.R1 v1(68.33,28.29) ; U6.A9 75.53,40.29 v1(75.53,40.29) ; U5.J5 v1(53.53,33.49) U5.H5 ; U5.L5 v1(53.53,35.09) U5.K5 ; v1(75.53,37.09) 75.53,37.09 U6.E9 ; U5.F5 v1(53.53,31.89) U5.G5 ; v1(73.93,37.89) 73.53,38.29 U6.C7 ; U6.A1 v1(68.33,40.29) ; 75.53,30.69 U6.M9 ; U5.E5 v1(53.53,30.29) ; U6.G7 v1(73.93,35.49) ; U6.G1 v1(68.33,35.49) ; U6.C3 v1(69.93,38.69) ; v1(75.53,35.49) 75.53,35.49 U6.G9 ; U6.C1 v1(68.33,38.69) ; v1(75.53,37.89) 75.13,38.29 U6.C9 ; U6.E1 v1(68.33,37.09) ; U6.G3 v1(69.93,35.49) ; 75.53,33.09 U6.J9
  TOP w0.381: v1(75.53,37.89) 76.33,38.69 C110.1 ; TP18.1 77.43,28.45 C117.1 C115.1 v1(76.71,30.69) 75.53,30.69 75.53,30.69 ; C112.1 v1(75.53,35.49) ; C109.1 v1(75.53,40.29) ; 75.53,33.09 v1(76.71,33.09) C113.1 C114.1 ; C89.2 v1(75.88,42.55) ; C111.1 v1(75.53,37.09) ; C116.1 v1(68.39,42.55)
  LYR3 w0.381: v1(71.75,8.26) 71.75,3.81 71.12,3.17 21.46,3.17 20.95,3.68 20.95,5.65 v1(21.27,5.97)
  LYR4 w0.381: v1(71.75,8.26) 68.45,11.56 68.45,22.73 v1(69.34,23.62)
  BOTTOM w0.305: v1(53.53,30.29) 53.53,30.98 C93.1 ; C92.1 53.53,32.58 v1(53.53,31.89) ; C90.1 53.53,35.78 v1(53.53,35.09) ; C91.1 53.53,34.18 v1(53.53,33.49)
  BOTTOM w0.381: C96.1 C91.1 ; C94.1 v1(75.88,42.55) ; C105.1 v1(68.33,37.09) ; C95.1 v1(68.39,42.55) ; R74.1 v1(64.01,32.7) ; C104.1 v1(68.33,38.69) ; C108.1 v1(68.33,28.29) ; C107.1 v1(68.33,33.09) ; C106.1 v1(68.33,35.49) ; C103.1 v1(68.33,40.29) ; R14.2 21.84,6.54 v1(21.27,5.97)
AIN0: length 34.4
  TOP w0.121: U5.B6 51.93,27.89 51.93,27.24 52.32,26.85 52.32,25.33 52.46,25.2 52.46,21.72 52.29,21.55 52.29,20.74 52.7,20.32 v1(53.21,20.32)
  LYR4 w0.133: P9.39 66.67,3.17 66.67,4.95 65.66,5.97 64.64,5.97 56.77,13.84 56.77,17.14 53.59,20.32 v1(53.21,20.32)
AIN1: length 32.9
  TOP w0.121: v1(51.93,28.69) U5.C7
  LYR4 w0.133: v1(51.93,28.69) 51.93,21.22 52.38,20.78 53.52,20.78 57.02,17.27 57.02,13.97 64.77,6.22 66.17,6.22 P9.40
AIN2: length 33.1
  TOP w0.121: v1(53.21,19.05) 51.79,20.47 51.79,21.89 51.96,22.06 51.96,24.99 51.82,25.14 51.82,26.59 51.13,27.28 51.13,27.89 U5.B7
  LYR4 w0.133: P9.37 64.39,2.92 64.39,5.46 56.26,13.59 56.26,16.89 54.1,19.05 v1(53.21,19.05)
AIN3: length 29.5
  TOP w0.121: v1(53.21,19.68) 52.96,19.68 52.04,20.6 52.04,21.78 52.21,21.95 52.21,25.1 52.07,25.24 52.07,26.72 51.53,27.26 U5.A7
  LYR4 w0.133: v1(53.21,19.68) 53.85,19.68 56.52,17.02 56.52,13.72 65.41,4.83 P9.38
AIN4: length 32.2
  TOP w0.121: v1(51.13,28.69) U5.C8
  LYR4 w0.133: P9.33 61.59,3.17 61.59,6.1 55.5,12.19 55.5,14.1 52.7,16.89 52.7,19.94 51.56,21.08 51.56,28.26 v1(51.13,28.69)
AIN5: length 30.8
  TOP w0.121: U5.B8 50.33,27.89 50.33,27.14 50.67,26.8 50.67,25.53 51.47,24.73 51.47,22.26 51.3,22.09 51.3,19.69 v1(53.21,17.78)
  LYR4 w0.133: v1(53.21,17.78) 54.61,17.78 55.75,16.64 55.75,13.34 58.8,10.29 58.8,9.27 59.44,8.64 60.45,8.64 62.87,6.22 P9.36
AIN6: length 32.9
  TOP w0.121: U5.A8 50.73,27.25 51.56,26.42 51.56,25.04 51.71,24.89 51.71,22.16 51.55,21.99 51.55,20.08 v1(53.21,18.41)
  LYR4 w0.133: v1(53.21,18.41) 54.36,18.41 56.01,16.76 56.01,13.46 59.05,10.41 59.05,9.4 59.56,8.89 60.58,8.89 63.88,5.59 63.88,2.92 P9.35
AIN7: length 28.6
  TOP w0.121: v1(50.33,28.69) U5.C9
  LYR3 w0.133: v1(50.33,28.69) 50.33,26.07 49.76,25.5 38.71,25.5 38.23,25.02 36.2,25.02 35.43,24.26 30.92,24.26 30.67,24 30.67,23.56 30.35,23.24 28.83,23.24 v1(28.26,23.81)
  BOTTOM w0.121: R8.1 R9.2 v1(28.26,23.81)
BAT: length 25.1
  TOP w0.121: U2.5 21.63,17.11 21.46,17.27 ; 21.46,17.27 19.43,17.27 18.92,17.78 16.64,17.78 15.88,17.02 15.88,15.88 15.49,15.49 11.43,15.49 10.79,16.13 10.79,16.89 10.16,17.53 8,17.53 P6.1 ; 21.46,17.27 21.68,17.49 22.31,17.49 U2.4
  LYR3 w0.133: P6.2 P6.1
  BOTTOM w0.121: P6.1 6.99,15.49 7.37,15.11 C3.2
BAT_SENSE: length 14
  TOP w0.121: U2.6 21.03,16.71 20.57,16.26 18.41,16.26 17.27,15.11 10.92,15.11 P6.3
BAT_TEMP: length 16.5
  TOP w0.121: v1(21.46,13.97) 21.46,14.35 21.82,14.71 U2.11
  LYR3 w0.133: v1(21.46,13.97) 20.51,14.92 11.75,14.92 10.79,15.88 10.79,17.78 P6.4
BL_IN: length 17.9
  TOP w0.121: U2.37 28.35,19.58 28.7,19.94 28.7,20.57 27.18,22.1 20.32,22.1 18.54,20.32 15.88,20.32 P6.8
BL_ISET1: length 22.5
  TOP w0.121: 12.06,19.05 13.84,20.83 18.29,20.83 20.07,22.61 27.43,22.61 29.21,20.83 29.21,18.54 28.98,18.31 U2.35
BL_ISET2: length 23.2
  TOP w0.121: U2.36 28.47,19.18 28.96,19.66 28.96,20.7 27.3,22.35 20.19,22.35 19.81,21.96 19.79,21.96 19.27,21.44 19.27,21.42 18.41,20.57 14.48,20.57 13.34,19.43 13.34,17.78 12.06,16.51
BL_OUT: length 20.8
  TOP w0.121: U2.38 27.22,19.6 27.22,21.04 26.42,21.84 20.45,21.84 18.67,20.07 16.51,20.07 15.75,19.3 15.75,17.65 P6.7
  BOTTOM w0.121: C7.1 12.95,14.86 P6.7
BL_SINK1: length 22.2
  TOP w0.121: v1(18.03,21.34) 19.56,22.86 27.56,22.86 29.46,20.95 29.46,18.29 29.09,17.91 U2.34
  LYR3 w0.133: v1(18.03,21.34) 18.41,20.95 18.41,17.78 P6.9
BL_SINK2: length 20.9
  TOP w0.121: v1(17.14,21.34) 18.92,23.11 27.69,23.11 29.72,21.08 29.72,18.16 29.07,17.51 U2.33
  LYR3 w0.133: v1(17.14,21.34) P6.10
CAP_VBB_MPU: length 4.2
  TOP w0.121: U5.C10 48.74,28.7 v1(48.73,28.69)
  BOTTOM w0.121: v1(48.73,28.69) 48.73,27.47 49.21,26.99 C85.1
CAP_VDD_SRAM_CORE: length 5.2
  TOP w0.121: v1(50.33,29.49) U5.D9
  BOTTOM w0.121: C83.1 50.16,27.69 50.73,28.25 50.73,29.09 v1(50.33,29.49)
CAP_VDD_SRAM_MPU: length 5
  TOP w0.121: v1(47.93,29.49) U5.D11
  BOTTOM w0.121: C84.1 48.33,25.34 48.33,29.09 v1(47.93,29.49)
CD/EMU4: length 44.9
  TOP w0.121: v1(44.73,28.69) U5.C15 ; v1(62.36,16.51) v1(62.36,19.05)
  LYR3 w0.133: v1(66.04,21.34) 64.64,21.34 v1(62.36,19.05)
  BOTTOM w0.121: v1(44.73,28.69) 44.33,28.29 44.33,26.8 43.69,26.16 43.69,22.23 44.58,21.34 45.21,21.34 45.97,22.1 47.14,22.1 47.39,22.35 52.32,22.35 53.96,20.72 58.53,20.72 59.18,20.07 59.18,17.27 59.94,16.51 v1(62.36,16.51) ; v1(66.04,21.34) 68.33,21.34 69.34,20.32 R197.2 ; R185.1 60.45,18.8 60.71,19.05 v1(62.36,19.05)
CLKOUT2: length 44.7
  LYR4 w0.133: v1(66.04,20.32) 66.04,8.89 69.22,5.71 69.22,3.17 P9.41
  BOTTOM w0.121: R218.2 44.58,23.75 44.96,23.37 52.2,23.37 54.35,21.22 58.81,21.22 59.18,21.59 64.26,21.59 65.53,20.32 v1(66.04,20.32) R184.2
CLKOUT_SRC: length 7.1
  TOP w0.121: U5.D14 v1(45.53,29.49)
  BOTTOM w0.121: v1(45.53,29.49) 45.13,29.09 45.13,26.46 44.58,25.91 R218.1 44.96,25.27 45.09,25.15 45.09,24.38 45.21,24.26 R221.1
COL/CRS_DV/MODE2: length 3.3
  TOP w0.121: U15.15 29.06,33.64 29.46,34.04 29.46,34.42 29.81,34.77 30.45,34.77 R207.2
CRFILT: length 2.3
  TOP w0.121: C146.1 24.26,40.01 23.99,40.28 U11.9
CRS_DV/MODE2: length 7.7
  TOP w0.121: R139.2 v1(30.1,34.29) 30.1,34.04 29.2,33.14 U15.14
  BOTTOM w0.121: v1(30.1,34.29) R139.2 31.4,34.77 33.94,34.77 R127.1
DC_IN: length 1.8
  TOP w0.203: U2.10 21.46,15.11
  BOTTOM w0.381: v1(16.76,12.32) 16.64,12.19 C1.1
DDR_A0: length 26.8
  TOP w0.121: U6.M8 73.93,31.49 71.25,31.49 71.12,31.36 71.12,28.19 70.48,27.56 67.56,27.56 67.44,27.69 67.44,32.13 67.31,32.26 64.01,32.26 63.88,32.13 63.88,28.57 63.75,28.45 v1(62.23,28.45)
  BOTTOM w0.121: R29.1 61.79,28.89 v1(62.23,28.45)
DDR_A1: length 26.9
  TOP w0.121: R25.1 v1(62.23,31.75) ; U6.M3 v1(69.93,30.69)
  LYR3 w0.121: 68.58,31.89 69.3,31.89 69.53,31.66 69.53,31.09 v1(69.93,30.69)
  LYR3 w0.133: 68.58,31.89 68.51,31.89 68.5,31.9 68.16,31.9 68.16,31.89 65.91,31.89 65.79,31.76 65.79,26.92 65.66,26.8 63.75,26.8 63.63,26.67 63.63,24.38 63.5,24.26 62.61,24.26 62.48,24.38 62.48,27.94 62.61,28.07 63.5,28.07 63.63,28.19 63.63,30.99 63.5,31.11 62.36,31.11 62.23,31.24 v1(62.23,31.75)
DDR_A2: length 27.2
  TOP w0.121: v1(62.99,27.56) 63.25,27.56 64.14,28.45 64.14,31.88 64.26,32 67.06,32 67.18,31.88 67.18,27.43 67.31,27.3 70.64,27.3 72.14,28.8 72.14,29.34 72.01,29.46 71.5,29.46 71.37,29.59 71.37,30.96 71.5,31.09 U6.M7
  BOTTOM w0.121: R30.1 60.2,26.04 60.71,26.54 61.98,26.54 v1(62.99,27.56)
DDR_A3: length 27.2
  TOP w0.121: U6.N2 v1(69.13,29.89)
  BOTTOM w0.121: v1(69.13,29.89) 69.13,29.65 68.73,29.25 68.73,29.24 68.65,29.15 68.65,28.89 68.85,28.69 69.3,28.69 69.53,28.45 69.53,27.56 69.66,27.43 69.98,27.43 70.1,27.3 70.1,26.92 69.98,26.8 67.94,26.8 67.82,26.67 67.82,24.77 67.69,24.64 62.23,24.64 62.1,24.51 62.1,24.26 62.23,24.13 65.02,24.13 65.15,24 65.15,23.88 65.02,23.75 57.53,23.75 57.4,23.88 57.4,24.13 57.28,24.26 R26.1
DDR_A4: length 27
  TOP w0.121: v1(69.34,24.64) 68.83,24.13 67.18,24.13 66.78,24.53 63.52,24.53 61.66,22.67 R31.1 ; U6.N8 v1(74.73,29.89)
  LYR3 w0.133: v1(74.73,29.89) 74.73,30.61 74.86,30.73 76.07,30.73 76.2,30.61 76.2,28.32 76.07,28.19 74.93,28.19 74.8,28.32 74.8,28.83 74.68,28.96 73.53,28.96 72.01,27.43 71.5,27.43 70.99,26.92 70.99,25.53 70.1,24.64 v1(69.34,24.64)
DDR_A5: length 27.3
  TOP w0.121: R32.1 58.36,22.1 61.47,22.1 63.66,24.29 66.65,24.29 v1(67.31,23.62) ; U6.N3 v1(69.93,29.89)
  LYR3 w0.121: v1(69.93,29.89) 69.53,29.49 69.53,28.07
  LYR3 w0.133: v1(67.31,23.62) 67.44,23.75 67.44,26.42 67.31,26.54 66.67,26.54 66.55,26.67 66.55,30.73 66.67,30.86 67.44,30.86 67.56,30.73 67.56,28.19 67.94,27.81 69.28,27.81 69.53,28.07
DDR_A6: length 27.2
  TOP w0.121: U6.N7 v1(73.93,29.89)
  LYR3 w0.133: v1(70.36,26.04) 70.36,26.67 71.37,27.69 71.88,27.69 73.03,28.83 73.03,30.61 73.15,30.73 73.81,30.73 73.93,30.61 v1(73.93,29.89)
  BOTTOM w0.121: R33.1 54.93,23.69 55.39,23.22 69.7,23.22 70.74,24.26 70.74,25.65 v1(70.36,26.04)
DDR_A7: length 26.8
  TOP w0.121: R34.1 61.72,26.04 61.85,25.91 v1(66.8,25.91) ; U6.P2 v1(69.13,29.09)
  LYR3 w0.133: v1(69.13,29.09) 67.94,29.09 67.82,29.22 67.82,30.99 67.69,31.11 66.42,31.11 66.29,30.99 66.29,24.77 66.17,24.64 65.02,24.64 64.9,24.77 64.9,26.04 64.77,26.16 64.39,26.16 64.26,26.04 64.26,24.26 64.39,24.13 66.67,24.13 66.8,24.26 v1(66.8,25.91)
DDR_A8: length 27.2
  TOP w0.121: U6.P8 74.52,29.49 75.06,28.96 75.06,27.81 74.55,27.3 71.37,27.3 70.87,26.8 66.93,26.8 66.68,27.05 66.68,30.48 66.55,30.61 64.9,30.61 64.77,30.48 64.77,27.94 64.9,27.81 65.28,27.81 65.41,27.69 65.41,26.8 65.28,26.67 v1(62.99,26.67)
  BOTTOM w0.121: R35.1 60.13,25.08 61.09,26.04 62.36,26.04 v1(62.99,26.67)
DDR_A9: length 27.3
  TOP w0.121: U6.P3 v1(69.93,29.09) ; R36.1 61.79,23.18 63.39,24.78 68.18,24.78 v1(68.33,24.64)
  LYR3 w0.133: v1(69.93,29.09) 70.48,29.09 70.61,28.96 70.61,28.15 69.77,27.3 67.44,27.3 67.31,27.43 67.31,30.48 67.18,30.61 66.93,30.61 66.8,30.48 66.8,27.05 66.93,26.92 67.69,26.92 67.82,26.8 67.82,25.91 67.94,25.78 68.2,25.78 68.33,25.91 68.33,26.8 68.45,26.92 68.71,26.92 68.83,26.8 68.83,25.65 68.33,25.15 v1(68.33,24.64)
DDR_A10: length 27.2
  TOP w0.121: U6.M2 v1(69.13,30.69)
  BOTTOM w0.121: v1(69.13,30.69) 69.13,30.45 68.73,30.06 68.73,29.72 67.97,28.96 64.9,28.96 64.77,28.83 64.77,27.56 64.9,27.43 67.18,27.43 67.31,27.3 67.31,27.05 67.18,26.92 66.55,26.92 66.42,26.8 66.42,26.54 66.55,26.42 67.18,26.42 67.31,26.29 67.31,25.27 67.18,25.15 63.88,25.15 63.75,25.27 63.75,28.19 63.63,28.31 62.76,28.31 61.75,27.3 61.34,27.3 61.21,27.43 61.21,28.32 61.09,28.45 60.83,28.45 60.71,28.32 60.71,27.43 60.58,27.3 60.33,27.3 60.2,27.43 60.2,27.81 60.07,27.94 R37.1
DDR_A11: length 27.1
  TOP w0.121: R38.1 61.72,27.94 62.52,27.14 63.32,27.14 63.54,26.92 64.9,26.92 65.02,27.05 65.02,27.43 64.9,27.56 64.52,27.56 64.39,27.69 64.39,27.84 64.39,31.62 64.52,31.75 66.8,31.75 66.93,31.62 66.93,27.18 67.06,27.05 70.77,27.05 71.33,27.61 74.34,27.61 74.8,28.07 74.8,28.78 74.5,29.09 74.17,29.09 73.77,29.49 U6.P7
DDR_A12: length 27.1
  TOP w0.121: U6.R2 v1(69.13,28.29)
  BOTTOM w0.121: R39.1 61.79,26.99 62.87,28.07 63.37,28.07 63.5,27.94 63.5,25.53 63.37,25.4 61.47,25.4 61.34,25.27 61.34,24.64 61.21,24.51 59.69,24.51 59.56,24.38 59.56,24.13 59.69,24 61.72,24 61.85,24.13 61.85,24.77 61.98,24.89 67.44,24.89 67.56,25.02 67.56,27.56 67.69,27.69 68.33,27.69 68.45,27.56 68.45,27.18 68.58,27.05 69.01,27.05 69.13,27.18 v1(69.13,28.29)
DDR_A13: length 27.1
  BOTTOM w0.121: R120.1 66.22,30.23 66.35,30.1 67.31,30.1 67.44,29.97 67.44,29.72 67.31,29.59 65.41,29.59 65.28,29.72 65.28,32.13 64.88,32.53 64.88,33.4 64.75,33.53 64.53,33.53 64.41,33.4 64.41,32.49 64.77,32.13 64.77,29.72 64.64,29.59 64.39,29.59 64.26,29.72 64.26,32 64.14,32.13 63.88,32.13 63.75,32 63.75,30.82 63.63,30.69 63.37,30.69 63.25,30.82 63.25,31.24 63.14,31.35 62.87,31.35 62.74,31.22 62.74,30.82 62.61,30.69 62.36,30.69 62.23,30.82 62.23,31.24 62.1,31.37 61.85,31.37 61.72,31.24 61.72,30.82 61.59,30.69 61.34,30.69 61.21,30.82 61.21,32 61.09,32.13 60.83,32.13 60.71,32 60.71,30.82 60.58,30.69 60.33,30.69 60.2,30.82 60.2,31.62 60.07,31.75 R40.1
DDR_A13R: length 7.9
  TOP w0.121: v1(72.07,30.29) 73.27,29.09 73.7,29.09 74.1,28.69 U6.R8
  LYR3 w0.121: v1(68.33,30.69) 68.73,30.29 70.17,30.29
  LYR3 w0.133: v1(72.07,30.29) 70.17,30.29
  BOTTOM w0.121: R120.2 v1(68.33,30.69)
DDR_BA0: length 26.9
  TOP w0.121: U6.L2 v1(69.13,31.49)
  BOTTOM w0.121: R41.1 55.88,23.75 56.13,23.5 65.41,23.5 65.53,23.62 65.53,23.89 65.66,24.02 69.74,24.02 70.36,24.64 70.36,25.15 70.23,25.27 68.83,25.27 68.71,25.4 68.71,26.42 68.83,26.54 70.23,26.54 70.36,26.67 70.36,28.45 70.12,28.69 69.77,28.69 69.53,28.92 69.53,31.09 v1(69.13,31.49)
DDR_BA1: length 26.9
  TOP w0.121: U6.L3 v1(69.93,31.49) ; R42.1 61.79,26.99 62.61,26.16 65.66,26.16 65.79,26.29 65.79,28.7 65.66,28.83 65.53,28.83 65.41,28.96 65.41,30.1 65.53,30.23 66.17,30.23 66.29,30.1 66.29,26.54 66.42,26.42 68.96,26.42 v1(69.34,26.04)
  LYR3 w0.133: v1(69.93,31.49) 71.76,31.49 72.52,30.73 72.52,29.21 71.5,28.19 70.99,28.19 69.87,27.07 69.47,27.07 69.34,26.94 v1(69.34,26.04)
DDR_BA2: length 27.1
  TOP w0.121: v1(66.04,23.62) 63.75,23.62 61.72,21.59 56.96,21.59 R43.1 ; U6.L1 v1(68.33,31.49)
  LYR3 w0.133: v1(68.33,31.49) 66.17,31.49 66.04,31.36 66.04,26.16 65.91,26.04 65.41,26.04 65.28,26.16 65.28,26.42 65.15,26.54 64.01,26.54 63.88,26.42 63.88,23.75 64.01,23.62 v1(66.04,23.62)
DDR_CASN: length 26.9
  TOP w0.121: R64.1 61.21,28.96 63.41,28.96 63.54,29.08 63.54,33.11 63.66,33.24 64.52,33.24 64.64,33.37 64.64,33.53 64.77,33.66 67.56,33.66 67.69,33.53 67.69,27.94 67.82,27.81 70.36,27.81 70.87,28.32 70.87,32.27 70.99,32.4 73.03,32.4 U6.L7
DDR_CKE: length 27.1
  TOP w0.121: U6.K2 v1(69.13,32.29)
  BOTTOM w0.121: R62.1 60.01,30.35 63.63,30.35 63.75,30.23 63.75,29.34 63.63,29.21 63.12,29.21 62.99,29.08 62.99,28.83 63.12,28.7 64.01,28.7 64.14,28.57 64.14,25.53 64.26,25.4 64.52,25.4 64.64,25.53 64.64,26.54 64.77,26.67 65.02,26.67 65.15,26.54 65.15,25.53 65.28,25.4 65.66,25.4 65.79,25.53 65.79,26.92 65.66,27.05 64.64,27.05 64.52,27.18 64.52,29.08 64.64,29.21 67.56,29.21 67.82,29.46 67.82,30.04 68.07,30.29 68.29,30.29 68.5,30.29 68.73,30.52 68.73,31.89 v1(69.13,32.29)
DDR_CLK: length 27.1
  TOP w0.095: R60.1 61.49,24.47 62.06,24.47 62.74,25.15 70.74,25.15 v1(71.63,26.04)
  TOP w0.121: v1(74.73,33.09) 74.33,33.49 U6.J8
  LYR3 w0.102: v1(71.63,26.04) 72.31,26.04 73.66,27.38 77.6,27.38 78.16,27.94 78.16,31.95 77.57,32.54 76.48,32.54 75.93,33.09 v1(74.73,33.09)
DDR_CLKN: length 27
  TOP w0.095: R61.1 61.49,24.75 61.94,24.75 62.62,25.43 70.62,25.43 71.22,26.03 71.22,26.54 71.35,26.67 v1(71.63,26.67)
  TOP w0.121: U6.K8 74.33,32.69 v1(74.73,32.29)
  LYR3 w0.102: v1(71.63,26.67) 71.96,26.34 72.19,26.34 73.53,27.69 77.47,27.69 77.85,28.07 77.85,31.83 77.45,32.23 76.35,32.23 75.8,32.79 74.98,32.79 74.73,32.54 v1(74.73,32.29)
